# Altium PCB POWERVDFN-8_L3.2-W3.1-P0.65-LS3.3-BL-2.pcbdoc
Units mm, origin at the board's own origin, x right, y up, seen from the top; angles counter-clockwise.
Board outline 16.2 x 16.66 mm, 2 copper layers (Top Layer, Bottom Layer), stack 0 mm thick; 1 components, 0 nets, 9 pads, 0 vias.
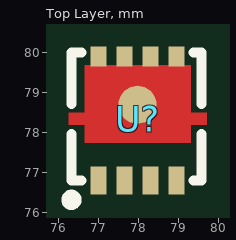
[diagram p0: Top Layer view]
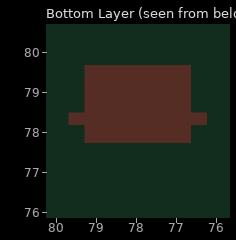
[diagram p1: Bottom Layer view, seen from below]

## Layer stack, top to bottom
Top Layer: signal copper (thickness not stored)
Bottom Layer: signal copper (thickness not stored)

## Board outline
86.053,69.85 69.85,69.85 69.85,86.509 86.053,86.509

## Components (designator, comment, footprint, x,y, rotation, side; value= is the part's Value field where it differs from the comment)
U? "" POWERVDFN-8_L3.2-W3.1-P0.65-LS3.3-BL-2 77.978,78.359 r0 top

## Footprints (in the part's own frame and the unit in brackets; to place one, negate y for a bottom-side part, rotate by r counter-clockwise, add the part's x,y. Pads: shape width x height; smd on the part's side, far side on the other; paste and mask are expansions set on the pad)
POWERVDFN-8_L3.2-W3.1-P0.65-LS3.3-BL-2 [mm]
  rect 0.4x0.7 smd paste-100 mask+0.05: 1(-0.975,-1.55) 2(-0.325,-1.55) 3(0.325,-1.55) 4(0.975,-1.55)
  rect 0.4x0.5 smd paste-100 mask+0.05: 5(0.975,1.55) 6(0.325,1.55) 7(-0.325,1.55) 8(-0.975,1.55)
  round 0.954 smd: 8(0,0.343)
  Top Layer region: 1.325,-0.61 -1.325,-0.61 -1.325,-0.16 -1.725,-0.16 -1.725,0.14 -1.325,0.14 -1.325,1.33 1.325,1.33 1.325,0.14 1.725,0.14 1.725,-0.16 1.325,-0.16
  silkscreen extent -1.78,-2.16 1.6,1.65

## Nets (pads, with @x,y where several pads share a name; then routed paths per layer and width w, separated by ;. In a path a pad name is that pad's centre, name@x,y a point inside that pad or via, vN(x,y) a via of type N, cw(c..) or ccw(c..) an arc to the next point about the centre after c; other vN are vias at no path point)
pads on no net: U?.1 U?.2 U?.3 U?.4 U?.5 U?.6 U?.7 U?.8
